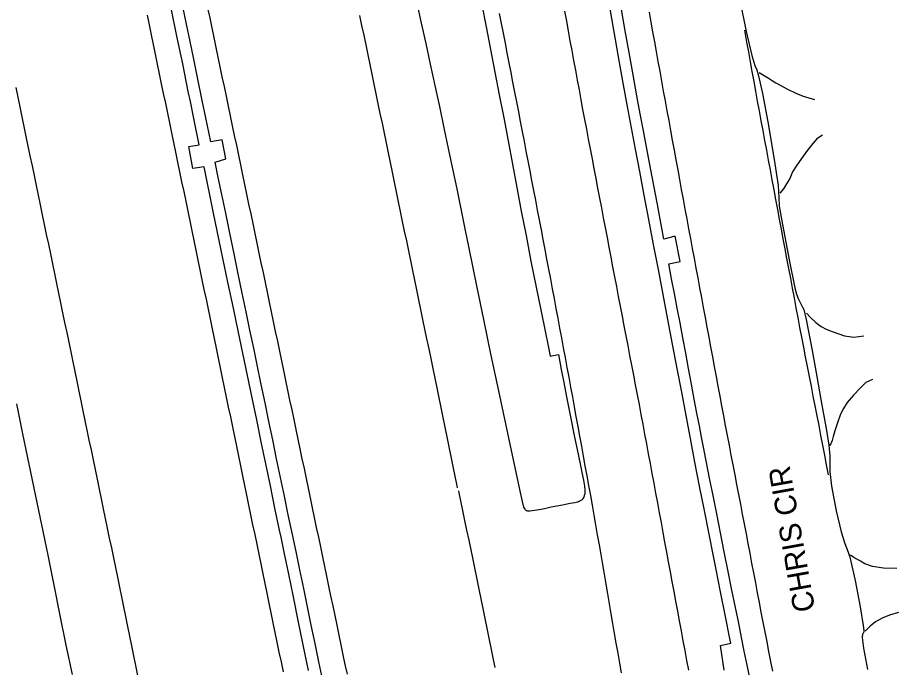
# Model space of a CAD drawing. Extents: x 1948091 to 1975253, y 787267 to 823306.
# Drawn here: x 1966724.5 to 1966944.4, y 788634.5 to 788796.8 of the extents above; entities that cross this region are included whole.
import ezdxf

# ---------------------------------------------------------------- set-up
doc = ezdxf.new("R2010")
doc.units = 0
for name, color, linetype in [('RD_EX_Pavement_Markings', 7, 'Continuous'), ('RD_EX_Road', 7, 'Continuous'), ('RD_TX_RoadID', 7, 'Continuous')]:
    doc.layers.add(name, color=color, linetype=linetype)

msp = doc.modelspace()

# ---------------------------------------------------------------- linework, layer by layer
at = {"layer": 'RD_EX_Pavement_Markings'}
for points in [[(1966756.79, 788797.43), (1966757.29, 788794.98), (1966757.8, 788792.53), (1966758.31, 788790.09), (1966758.82, 788787.64), (1966759.33, 788785.19), (1966759.83, 788782.74), (1966760.34, 788780.3), (1966760.85, 788777.85), (1966761.36, 788775.4), (1966761.86, 788772.95), (1966762.37, 788770.5), (1966762.88, 788768.06), (1966763.39, 788765.61), (1966763.9, 788763.16), (1966764.4, 788760.71), (1966764.91, 788758.26), (1966765.42, 788755.82), (1966765.93, 788753.37), (1966766.43, 788750.92), (1966766.94, 788748.47), (1966767.45, 788746.03), (1966767.96, 788743.58), (1966768.47, 788741.13), (1966768.97, 788738.68), (1966769.48, 788736.23), (1966769.99, 788733.79), (1966770.5, 788731.34), (1966771, 788728.89), (1966771.51, 788726.44), (1966772.02, 788724), (1966772.53, 788721.55), (1966773.04, 788719.1), (1966773.54, 788716.65), (1966774.05, 788714.2), (1966774.55, 788711.75), (1966775.06, 788709.31), (1966775.57, 788706.86), (1966776.07, 788704.41), (1966776.58, 788701.96), (1966777.08, 788699.51), (1966777.59, 788697.07), (1966778.1, 788694.62), (1966778.6, 788692.17), (1966779.11, 788689.72), (1966779.61, 788687.27), (1966780.12, 788684.82), (1966780.62, 788682.38), (1966781.13, 788679.93), (1966781.64, 788677.48), (1966782.14, 788675.03), (1966782.65, 788672.58), (1966783.15, 788670.14), (1966783.66, 788667.69), (1966784.17, 788665.24), (1966784.67, 788662.79), (1966785.18, 788660.34), (1966785.68, 788657.89), (1966786.19, 788655.45), (1966786.7, 788653), (1966787.2, 788650.55), (1966787.71, 788648.1), (1966788.21, 788645.65), (1966788.72, 788643.2), (1966789.22, 788640.76), (1966789.73, 788638.31), (1966790.24, 788635.86), (1966790.74, 788633.41)], [(1966771.91, 788799.17), (1966772.42, 788796.72), (1966772.93, 788794.28), (1966773.44, 788791.83), (1966773.95, 788789.38), (1966774.47, 788786.94), (1966774.98, 788784.49), (1966775.49, 788782.04), (1966776, 788779.59), (1966776.52, 788777.15), (1966777.03, 788774.7), (1966777.54, 788772.25), (1966778.05, 788769.81), (1966778.57, 788767.36), (1966779.08, 788764.91), (1966779.59, 788762.47), (1966780.1, 788760.02), (1966780.61, 788757.57), (1966781.13, 788755.13), (1966781.64, 788752.68), (1966782.15, 788750.23), (1966782.66, 788747.78), (1966783.18, 788745.34), (1966783.69, 788742.89), (1966784.2, 788740.44), (1966784.71, 788738), (1966785.23, 788735.55), (1966785.74, 788733.1), (1966786.25, 788730.66), (1966786.76, 788728.21), (1966787.27, 788725.76), (1966787.79, 788723.32), (1966788.3, 788720.87), (1966788.81, 788718.42), (1966789.32, 788715.98), (1966789.84, 788713.53), (1966790.35, 788711.08), (1966790.86, 788708.63), (1966791.37, 788706.19), (1966791.88, 788703.74), (1966792.39, 788701.29), (1966792.91, 788698.85), (1966793.42, 788696.4), (1966793.93, 788693.95), (1966794.44, 788691.51), (1966794.95, 788689.06), (1966795.46, 788686.61), (1966795.98, 788684.16), (1966796.49, 788681.72), (1966797, 788679.27), (1966797.51, 788676.82), (1966798.02, 788674.38), (1966798.53, 788671.93), (1966799.05, 788669.48), (1966799.56, 788667.03), (1966800.07, 788664.59), (1966800.58, 788662.14), (1966801.09, 788659.69), (1966801.6, 788657.25), (1966802.12, 788654.8), (1966802.63, 788652.35), (1966803.14, 788649.91), (1966803.65, 788647.46), (1966804.16, 788645.01), (1966804.67, 788642.56), (1966805.18, 788640.12), (1966805.69, 788637.67), (1966806.2, 788635.22), (1966806.71, 788632.77)], [(1966844.73, 788797.82), (1966845.2, 788795.37), (1966845.68, 788792.92), (1966846.16, 788790.46), (1966846.63, 788788.01), (1966847.11, 788785.55), (1966847.59, 788783.1), (1966848.06, 788780.65), (1966848.54, 788778.19), (1966849.01, 788775.74), (1966849.49, 788773.29), (1966849.97, 788770.83), (1966850.44, 788768.38), (1966850.92, 788765.92), (1966851.39, 788763.47), (1966851.87, 788761.02), (1966852.34, 788758.56), (1966852.81, 788756.11), (1966853.28, 788753.65), (1966853.75, 788751.2), (1966854.21, 788748.74), (1966854.68, 788746.28), (1966855.15, 788743.83), (1966855.62, 788741.37), (1966856.09, 788738.92), (1966856.55, 788736.46), (1966857.02, 788734.01), (1966857.49, 788731.55), (1966857.95, 788729.09), (1966858.4, 788726.64), (1966858.86, 788724.18), (1966859.32, 788721.72), (1966859.77, 788719.26), (1966860.23, 788716.8), (1966860.69, 788714.35), (1966861.14, 788711.89), (1966861.6, 788709.43), (1966862.06, 788706.97), (1966862.51, 788704.51), (1966862.97, 788702.06), (1966863.42, 788699.6), (1966863.87, 788697.14), (1966864.32, 788694.68), (1966864.77, 788692.22), (1966865.22, 788689.76), (1966865.67, 788687.3), (1966866.13, 788684.84), (1966866.58, 788682.38), (1966867.03, 788679.93), (1966867.48, 788677.47), (1966867.93, 788675.01), (1966868.36, 788672.55), (1966868.78, 788670.08), (1966869.2, 788667.62), (1966869.63, 788665.15), (1966870.05, 788662.69), (1966870.47, 788660.22), (1966870.89, 788657.76), (1966871.31, 788655.3), (1966871.73, 788652.83), (1966872.15, 788650.37), (1966872.57, 788647.9), (1966872.99, 788645.44), (1966873.43, 788642.98), (1966873.86, 788640.52), (1966874.3, 788638.05), (1966874.73, 788635.59), (1966875.17, 788633.13)], [(1966892.03, 788633.8), (1966891.57, 788636.25), (1966891.12, 788638.71), (1966890.66, 788641.17), (1966890.21, 788643.63), (1966889.75, 788646.09), (1966889.29, 788648.54), (1966888.84, 788651), (1966888.38, 788653.46), (1966887.93, 788655.92), (1966887.47, 788658.38), (1966887.01, 788660.83), (1966886.56, 788663.29), (1966886.1, 788665.75), (1966885.65, 788668.21), (1966885.19, 788670.67), (1966884.74, 788673.12), (1966884.28, 788675.58), (1966883.83, 788678.04), (1966883.37, 788680.5), (1966882.92, 788682.96), (1966882.46, 788685.41), (1966882, 788687.87), (1966881.55, 788690.33), (1966881.09, 788692.79), (1966880.64, 788695.25), (1966880.18, 788697.7), (1966879.7, 788700.16), (1966879.23, 788702.61), (1966878.76, 788705.07), (1966878.29, 788707.52), (1966877.82, 788709.98), (1966877.35, 788712.43), (1966876.88, 788714.89), (1966876.41, 788717.34), (1966875.94, 788719.8), (1966875.47, 788722.26), (1966874.99, 788724.71), (1966874.52, 788727.17), (1966874.05, 788729.62), (1966873.58, 788732.08), (1966873.11, 788734.53), (1966872.64, 788736.99), (1966872.17, 788739.44), (1966871.71, 788741.9), (1966871.24, 788744.35), (1966870.77, 788746.81), (1966870.3, 788749.26), (1966869.84, 788751.72), (1966869.37, 788754.17), (1966868.9, 788756.63), (1966868.43, 788759.09), (1966867.97, 788761.54), (1966867.5, 788764), (1966867.03, 788766.45), (1966866.56, 788768.91), (1966866.09, 788771.36), (1966865.63, 788773.82), (1966865.18, 788776.28), (1966864.72, 788778.74), (1966864.27, 788781.19), (1966863.82, 788783.65), (1966863.37, 788786.11), (1966862.91, 788788.57), (1966862.46, 788791.03), (1966862.01, 788793.49), (1966861.56, 788795.94), (1966861.1, 788798.4)], [(1966882.15, 788798.17), (1966882.58, 788795.7), (1966883.01, 788793.24), (1966883.46, 788790.78), (1966883.9, 788788.32), (1966884.35, 788785.86), (1966884.79, 788783.4), (1966885.24, 788780.94), (1966885.68, 788778.48), (1966886.13, 788776.02), (1966886.58, 788773.56), (1966887.03, 788771.11), (1966887.48, 788768.65), (1966887.92, 788766.19), (1966888.37, 788763.73), (1966888.82, 788761.27), (1966889.27, 788758.81), (1966889.72, 788756.35), (1966890.17, 788753.89), (1966890.62, 788751.43), (1966891.07, 788748.97), (1966891.52, 788746.51), (1966891.97, 788744.05), (1966892.43, 788741.6), (1966892.9, 788739.14), (1966893.36, 788736.68), (1966893.82, 788734.23), (1966894.29, 788731.77), (1966894.75, 788729.31), (1966895.21, 788726.86), (1966895.67, 788724.4), (1966896.12, 788721.94), (1966896.57, 788719.48), (1966897.03, 788717.02), (1966897.48, 788714.57), (1966897.94, 788712.11), (1966898.39, 788709.65), (1966898.86, 788707.19), (1966899.32, 788704.74), (1966899.78, 788702.28), (1966900.24, 788699.82), (1966900.7, 788697.36), (1966901.16, 788694.91), (1966901.63, 788692.45), (1966902.1, 788690), (1966902.57, 788687.54), (1966903.04, 788685.09), (1966903.51, 788682.63), (1966903.98, 788680.18), (1966904.45, 788677.72), (1966904.92, 788675.27), (1966905.39, 788672.81), (1966905.86, 788670.35), (1966906.33, 788667.9), (1966906.8, 788665.44), (1966907.27, 788662.99), (1966907.73, 788660.53), (1966908.2, 788658.08), (1966908.67, 788655.62), (1966909.13, 788653.16), (1966909.6, 788650.71), (1966910.06, 788648.25), (1966910.53, 788645.8), (1966911.01, 788643.34), (1966911.49, 788640.89), (1966911.98, 788638.44), (1966912.47, 788635.98), (1966912.95, 788633.53)], [(1966809.86, 788797.33), (1966810.37, 788794.88), (1966810.88, 788792.44), (1966811.39, 788789.99), (1966811.89, 788787.54), (1966812.4, 788785.09), (1966812.91, 788782.65), (1966813.42, 788780.2), (1966813.93, 788777.75), (1966814.44, 788775.3), (1966814.94, 788772.85), (1966815.45, 788770.41), (1966815.96, 788767.96), (1966816.46, 788765.51), (1966816.97, 788763.06), (1966817.48, 788760.61), (1966817.98, 788758.17), (1966818.49, 788755.72), (1966819, 788753.27), (1966819.5, 788750.82), (1966820.01, 788748.37), (1966820.52, 788745.92), (1966821.02, 788743.48), (1966821.53, 788741.03), (1966822.04, 788738.58), (1966822.54, 788736.13), (1966823.05, 788733.68), (1966823.56, 788731.24), (1966824.06, 788728.79), (1966824.57, 788726.34), (1966825.07, 788723.89), (1966825.58, 788721.44), (1966826.09, 788719), (1966826.59, 788716.55), (1966827.1, 788714.1), (1966827.61, 788711.65), (1966828.11, 788709.2), (1966828.62, 788706.76), (1966829.13, 788704.31), (1966829.63, 788701.86), (1966830.14, 788699.41), (1966830.65, 788696.96), (1966831.15, 788694.52), (1966831.66, 788692.07), (1966832.17, 788689.62), (1966832.67, 788687.17), (1966833.16, 788684.72), (1966833.65, 788682.27), (1966834.14, 788679.82), (1966834.23, 788679.34)], [(1966926.93, 788682.62), (1966926.45, 788685.07), (1966925.98, 788687.53), (1966925.5, 788689.98), (1966925.03, 788692.44), (1966924.56, 788694.89), (1966924.08, 788697.35), (1966923.61, 788699.8), (1966923.13, 788702.25), (1966922.65, 788704.71), (1966922.18, 788707.16), (1966921.7, 788709.62), (1966921.22, 788712.07), (1966920.75, 788714.52), (1966920.27, 788716.98), (1966919.79, 788719.43), (1966919.33, 788721.89), (1966918.87, 788724.35), (1966918.41, 788726.8), (1966917.95, 788729.26), (1966917.48, 788731.72), (1966917.02, 788734.17), (1966916.56, 788736.63), (1966916.1, 788739.09), (1966915.64, 788741.54), (1966915.18, 788744), (1966914.71, 788746.46), (1966914.25, 788748.92), (1966913.79, 788751.37), (1966913.33, 788753.83), (1966912.88, 788756.29), (1966912.42, 788758.75), (1966911.96, 788761.2), (1966911.51, 788763.66), (1966911.05, 788766.12), (1966910.59, 788768.58), (1966910.14, 788771.04), (1966909.68, 788773.49), (1966909.23, 788775.95), (1966908.78, 788778.41), (1966908.34, 788780.87), (1966907.89, 788783.33), (1966907.44, 788785.79), (1966907, 788788.25), (1966906.55, 788790.71), (1966906.1, 788793.17), (1966906.01, 788793.67)], [(1966724, 788779.39), (1966724.5, 788776.94), (1966725.01, 788774.49), (1966725.52, 788772.04), (1966726.03, 788769.6), (1966726.54, 788767.15), (1966727.05, 788764.7), (1966727.56, 788762.25), (1966728.07, 788759.8), (1966728.58, 788757.36), (1966729.08, 788754.91), (1966729.59, 788752.46), (1966730.1, 788750.01), (1966730.61, 788747.57), (1966731.12, 788745.12), (1966731.63, 788742.67), (1966732.14, 788740.22), (1966732.65, 788737.78), (1966733.16, 788735.33), (1966733.66, 788732.88), (1966734.17, 788730.43), (1966734.68, 788727.99), (1966735.19, 788725.54), (1966735.7, 788723.09), (1966736.21, 788720.64), (1966736.72, 788718.19), (1966737.22, 788715.75), (1966737.73, 788713.3), (1966738.24, 788710.85), (1966738.75, 788708.4), (1966739.25, 788705.96), (1966739.76, 788703.51), (1966740.27, 788701.06), (1966740.77, 788698.61), (1966741.28, 788696.16), (1966741.79, 788693.72), (1966742.29, 788691.27), (1966742.8, 788688.82), (1966743.31, 788686.37), (1966743.81, 788683.92), (1966744.32, 788681.48), (1966744.83, 788679.03), (1966745.34, 788676.58), (1966745.84, 788674.13), (1966746.35, 788671.68), (1966746.86, 788669.24), (1966747.36, 788666.79), (1966747.87, 788664.34), (1966748.38, 788661.89), (1966748.88, 788659.44), (1966749.39, 788657), (1966749.9, 788654.55), (1966750.4, 788652.1), (1966750.91, 788649.65), (1966751.41, 788647.2), (1966751.92, 788644.75), (1966752.42, 788642.3), (1966752.93, 788639.86), (1966753.43, 788637.41), (1966753.93, 788634.96), (1966754.44, 788632.51)], [(1966843.7, 788634.47), (1966843.19, 788636.92), (1966842.69, 788639.37), (1966842.19, 788641.82), (1966841.69, 788644.27), (1966841.18, 788646.72), (1966840.68, 788649.17), (1966840.18, 788651.62), (1966839.68, 788654.07), (1966839.17, 788656.51), (1966838.67, 788658.96), (1966838.17, 788661.41), (1966837.67, 788663.86), (1966837.17, 788666.31), (1966836.66, 788668.76), (1966836.16, 788671.21), (1966835.66, 788673.66), (1966835.16, 788676.11), (1966834.65, 788678.55), (1966834.65, 788678.58)]]:
    msp.add_lwpolyline(points, dxfattribs=at)
at = {"layer": 'RD_EX_Road'}
for points in [[(1966800.64, 788631.24), (1966799.69, 788635.85), (1966798.74, 788640.46), (1966797.79, 788645.06), (1966796.84, 788649.65), (1966795.89, 788654.24), (1966794.94, 788658.84), (1966793.98, 788663.43), (1966793.09, 788667.7), (1966792.05, 788672.63), (1966791.09, 788677.27), (1966790.12, 788681.93), (1966789.14, 788686.63), (1966788.17, 788691.31), (1966787.21, 788695.96), (1966786.26, 788700.57), (1966785.31, 788705.13), (1966784.37, 788709.68), (1966783.42, 788714.22), (1966782.47, 788718.77), (1966781.52, 788723.32), (1966780.55, 788727.95), (1966779.55, 788732.77), (1966778.52, 788737.77), (1966777.46, 788742.94), (1966776.43, 788748), (1966775.47, 788752.66), (1966774.58, 788756.9), (1966773.77, 788760.73), (1966776.48, 788761.52), (1966775.58, 788766.29), (1966772.73, 788765.77), (1966771.49, 788771.76), (1966770.58, 788776.13), (1966769.37, 788781.89), (1966768.43, 788786.45), (1966767.53, 788790.83), (1966766.62, 788795.21), (1966765.72, 788799.59)], [(1966840.37, 788800.02), (1966841.46, 788794.47), (1966842.55, 788788.86), (1966843.64, 788783.2), (1966844.74, 788777.5), (1966845.84, 788771.76), (1966846.93, 788766), (1966848.02, 788760.21), (1966849.1, 788754.4), (1966850.22, 788748.48), (1966851.4, 788742.35), (1966852.64, 788736.01), (1966853.95, 788729.47), (1966855.18, 788723.41), (1966856.17, 788718.52), (1966856.92, 788714.79), (1966857.44, 788712.24), (1966859.53, 788712.62), (1966860.22, 788708.89), (1966860.83, 788705.68), (1966861.54, 788702.07), (1966862.51, 788697.12), (1966863.53, 788691.98), (1966864.39, 788687.79), (1966865.07, 788684.52), (1966865.34, 788683.22), (1966865.74, 788681.23), (1966866, 788679.79), (1966866.12, 788678.79), (1966866.11, 788678.34), (1966866.06, 788677.89), (1966865.96, 788677.44), (1966865.82, 788677.03), (1966865.63, 788676.68), (1966865.39, 788676.39), (1966865.1, 788676.16), (1966864.79, 788675.98), (1966864.5, 788675.84), (1966864.22, 788675.74), (1966863.61, 788675.64), (1966862.41, 788675.43), (1966860.49, 788675.06), (1966857.7, 788674.48), (1966855.98, 788674.1), (1966855.19, 788673.95), (1966853.49, 788673.67), (1966852.39, 788673.53), (1966852.09, 788673.53), (1966851.88, 788673.55), (1966851.7, 788673.58), (1966851.54, 788673.64), (1966851.4, 788673.71), (1966851.28, 788673.82), (1966851.15, 788673.99), (1966851.03, 788674.23), (1966850.9, 788674.53), (1966850.5, 788675.96), (1966849.83, 788678.94), (1966848.91, 788683.25), (1966847.8, 788688.66), (1966846.39, 788695.37), (1966844.6, 788703.56), (1966842.69, 788712.39), (1966840.93, 788720.99), (1966839.16, 788729.79), (1966837.25, 788739.2), (1966836.25, 788744.09), (1966835.23, 788749.02), (1966834.19, 788754.01), (1966833.14, 788759.05), (1966832.06, 788764.15), (1966830.97, 788769.32), (1966829.86, 788774.57), (1966828.72, 788779.89), (1966827.58, 788785.2), (1966826.46, 788790.38), (1966825.35, 788795.46), (1966824.26, 788800.41)], [(1966900.9, 788633.8), (1966899.93, 788639.97), (1966902.52, 788640.53), (1966902.13, 788642.46), (1966901.6, 788645.1), (1966900.93, 788648.47), (1966900.12, 788652.55), (1966899.2, 788657.2), (1966899.1, 788657.72), (1966898.19, 788662.28), (1966897.11, 788667.77), (1966895.94, 788673.69), (1966894.75, 788679.77), (1966893.59, 788685.75), (1966892.46, 788691.64), (1966891.36, 788697.44), (1966890.27, 788703.25), (1966889.15, 788709.18), (1966888, 788715.22), (1966886.82, 788721.38), (1966885.63, 788727.61), (1966884.44, 788733.85), (1966883.25, 788740.1), (1966882.07, 788746.36), (1966880.91, 788752.49), (1966879.8, 788758.36), (1966878.73, 788763.96), (1966877.71, 788769.3), (1966876.71, 788774.58), (1966875.71, 788780.02), (1966874.71, 788785.62), (1966873.71, 788791.38), (1966872.82, 788796.56), (1966872.16, 788800.45)], [(1966904.91, 788800.78), (1966906.36, 788793.37), (1966907.75, 788787.32), (1966908.55, 788784.85), (1966909.04, 788783.8), (1966909.48, 788782.24), (1966910.48, 788777.89), (1966911.8, 788770.79), (1966913.4, 788761.35), (1966914.34, 788754.86), (1966914.53, 788751.91), (1966914.64, 788749.74), (1966915.44, 788745.12), (1966917.21, 788735.87), (1966918.56, 788729.3), (1966918.96, 788727.76), (1966919.34, 788726.67), (1966920.11, 788725.16), (1966920.47, 788724.52), (1966920.75, 788723.88), (1966921.33, 788721.43), (1966922.84, 788713.69), (1966924.01, 788707.13), (1966925.04, 788701.38), (1966926.41, 788693.69), (1966927, 788689.97), (1966927.27, 788687.23), (1966927.23, 788685.35), (1966927.25, 788683.41), (1966927.71, 788679.74), (1966928.87, 788673.58), (1966930.11, 788668.34), (1966931.02, 788665.41), (1966931.87, 788663.31), (1966932.28, 788662.04), (1966933.59, 788656.16), (1966934.82, 788649.65), (1966935.6, 788644.94), (1966935.75, 788643.75), (1966935.76, 788643.5), (1966935.73, 788643.37), (1966935.69, 788643.25), (1966935.64, 788643.15), (1966935.57, 788643.05), (1966935.5, 788642.93), (1966935.44, 788642.77), (1966935.4, 788642.56), (1966935.37, 788642.31), (1966935.37, 788641.96), (1966935.68, 788639.26), (1966936.68, 788633.99)], [(1966797.11, 788633.74), (1966795.79, 788640.12), (1966794.53, 788646.25), (1966793.31, 788652.14), (1966792.15, 788657.77), (1966791.01, 788663.28), (1966790.23, 788667.03), (1966789.87, 788668.79), (1966788.73, 788674.3), (1966787.59, 788679.81), (1966786.45, 788685.32), (1966785.31, 788690.83), (1966784.16, 788696.34), (1966783.01, 788701.85), (1966781.85, 788707.38), (1966780.69, 788712.96), (1966779.52, 788718.57), (1966778.34, 788724.23), (1966776.99, 788730.69), (1966775.32, 788738.73), (1966773.33, 788748.35), (1966771.01, 788759.55), (1966768.25, 788759.12), (1966767.18, 788764.62), (1966769.79, 788765.01), (1966768.45, 788771.65), (1966767.6, 788775.84), (1966767.09, 788778.39), (1966765.68, 788785.23), (1966764.25, 788792.17), (1966762.79, 788799.17)], [(1966907.37, 788631.43), (1966906.62, 788635.07), (1966905.91, 788638.59), (1966905.22, 788641.99), (1966904.5, 788645.53), (1966903.71, 788649.46), (1966902.83, 788653.78), (1966901.88, 788658.49), (1966900.9, 788663.35), (1966899.95, 788668.13), (1966899.01, 788672.83), (1966898.1, 788677.44), (1966897.25, 788681.78), (1966896.48, 788685.65), (1966895.81, 788689.06), (1966895.23, 788692), (1966894.68, 788694.86), (1966894.07, 788698.03), (1966893.42, 788701.5), (1966892.72, 788705.28), (1966891.99, 788709.18), (1966891.28, 788713.02), (1966890.57, 788716.81), (1966889.87, 788720.53), (1966889.17, 788724.23), (1966888.47, 788727.92), (1966887.76, 788731.6), (1966887.05, 788735.28), (1966889.88, 788735.85), (1966888.68, 788742.2), (1966885.85, 788741.5), (1966884.19, 788750.12), (1966882.86, 788757.05), (1966881.87, 788762.3), (1966881.2, 788765.85), (1966880.63, 788768.93), (1966879.94, 788772.74), (1966879.11, 788777.27), (1966878.16, 788782.52), (1966877.15, 788788.08), (1966876.17, 788793.53), (1966875.23, 788798.85)], [(1966909.6, 788783.13), (1966911.68, 788781.88), (1966913.77, 788780.56), (1966916.66, 788778.93), (1966918.79, 788777.96), (1966920.64, 788777.21), (1966923.43, 788776.39)], [(1966925.45, 788767.43), (1966924.02, 788766.54), (1966922.98, 788765.35), (1966921.68, 788763.66), (1966920.6, 788762.23), (1966919.04, 788759.95), (1966917.95, 788758.32), (1966917.25, 788756.62), (1966916.4, 788755.28), (1966915.66, 788754.08), (1966914.77, 788752.96)], [(1966921.41, 788722.98), (1966922.39, 788721.93), (1966923.77, 788720.64), (1966925.08, 788719.63), (1966926.33, 788718.97), (1966927.88, 788718.38), (1966930.91, 788717.34), (1966933.21, 788716.96), (1966935.74, 788717.34)], [(1966937.88, 788706.38), (1966936.28, 788705.63), (1966934.8, 788704.28), (1966933.14, 788702.51), (1966931.62, 788700.63), (1966930.66, 788699.14), (1966929.93, 788697.75), (1966929.14, 788695.55), (1966928.47, 788693.56), (1966928.1, 788692.16), (1966927.87, 788691.18), (1966927.48, 788690.32), (1966927.2, 788689.96)], [(1966724.18, 788700.37), (1966725.73, 788692.87), (1966727.3, 788685.3), (1966728.87, 788677.7), (1966730.43, 788670.11), (1966731.98, 788662.55), (1966733.51, 788655), (1966735.03, 788647.49), (1966736.55, 788640.07), (1966738.07, 788632.72)], [(1966943.96, 788659.23), (1966940.64, 788659.26), (1966937.91, 788659.68), (1966935.97, 788660.35), (1966934.89, 788660.99), (1966933.21, 788661.97), (1966932.43, 788662.53)], [(1966944.37, 788648.22), (1966942.16, 788647.53), (1966940.35, 788646.76), (1966938.66, 788645.88), (1966937.3, 788644.78), (1966936.11, 788643.55)]]:
    msp.add_lwpolyline(points, dxfattribs=at)

# ---------------------------------------------------------------- texts
at = {"layer": 'RD_TX_RoadID'}
msp.add_text('CHRIS CIR', height=5.4, rotation=100.0968, dxfattribs=at).set_placement((1966923.64, 788648.82))

doc.saveas('drawing.dxf')
